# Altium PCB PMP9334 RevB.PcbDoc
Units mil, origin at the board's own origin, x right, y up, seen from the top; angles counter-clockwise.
Board outline 4000 x 1100 mil, 4 copper layers (Top Layer, MidLayer1, GND, Bottom Layer), stack 62 mil thick; 51 components, 29 nets, 117 pads, 95 vias.
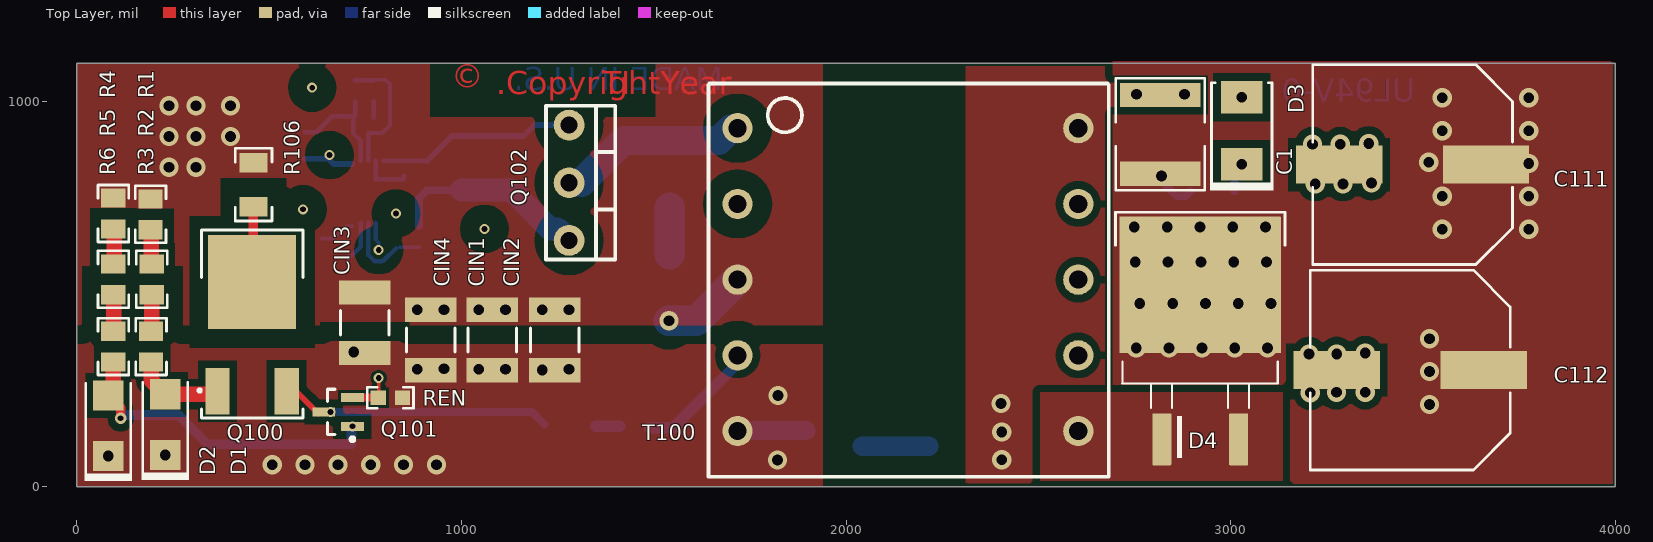
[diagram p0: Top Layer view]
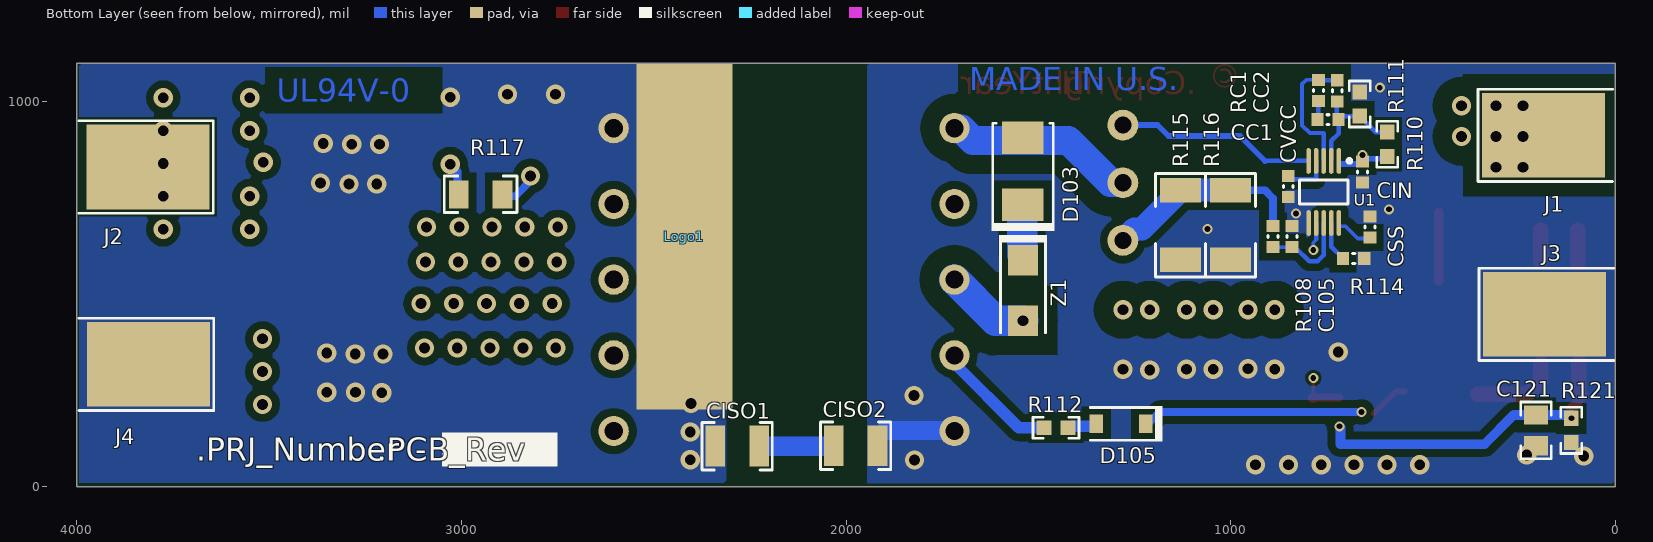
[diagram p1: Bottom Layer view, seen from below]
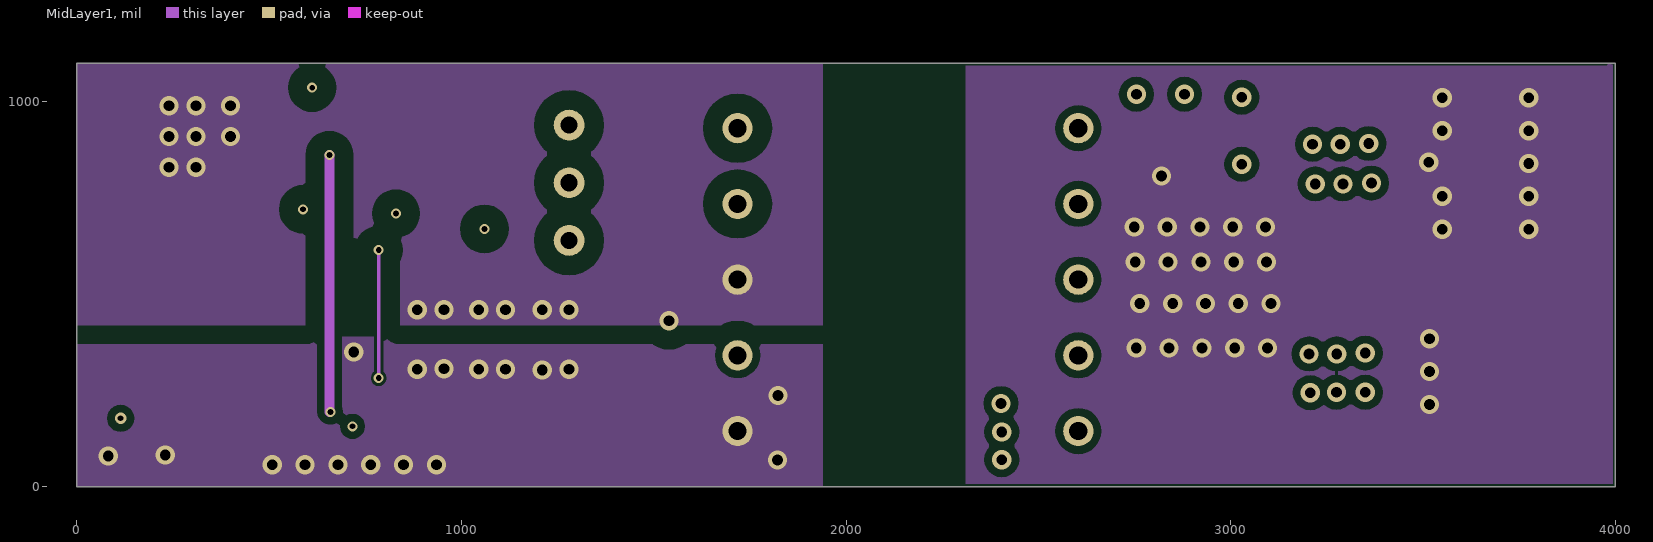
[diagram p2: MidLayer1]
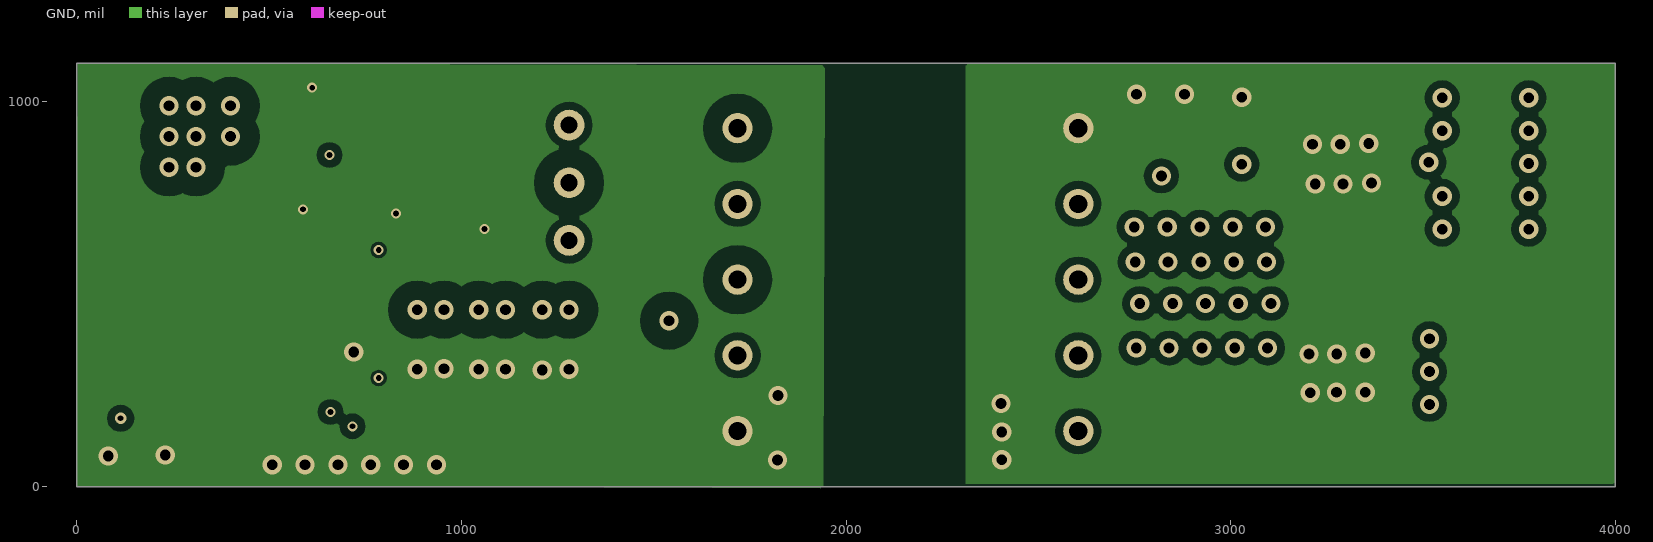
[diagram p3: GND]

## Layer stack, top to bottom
Top Solder: solder mask 0.4, Solder Resist, Dk 3.5
Top Layer: signal copper 1.4
Dielectric1: core 12.6, FR-4, Dk 4.8
MidLayer1: signal copper 0.7
Dielectric2: prepreg 32.6, FR-4, Dk 4.8
GND: signal copper 0.7
Dielectric3: core 12.6, FR-4, Dk 4.8
Bottom Layer: signal copper 1.4
Bottom Solder: solder mask 0.4, Solder Resist, Dk 3.5

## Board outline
0,0 4000,0 4000,1100 0,1100

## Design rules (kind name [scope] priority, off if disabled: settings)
AcuteAngle [All] p1: minimum=3.00000000000000E+0001 checktracksonly=FALSE
AssemblyTestPointUsage [All] p1: valid=2
Clearance Clearance_SYNC [InNet('SYNC') vs InNet('CS') or InNet('SS')] p1: gap=7.8
Clearance Clearance_UVLO [InNet('UVLO') vs InNet('CS') or InNet('GND')] p2: gap=7.8
Clearance Clearance_CS [InNet('CS') vs InNet('UVLO') or InNet('SYNC')] p3: gap=7.8
Clearance Clearance_FB [InNet('FB') vs InNet('VIN IC') or InNet('COMP')] p4: gap=7.8
Clearance Clearance_COMP [InNet('COMP') vs InNet('FB') or InNet('VCC')] p5: gap=7.8
Clearance Clearance_VCC [InNet('VCC') vs InNet('COMP') or InNet('OUT')] p6: gap=7.8
Clearance Clearance_MUB10A-N [HasFootprint('MUB10A_N') vs HasFootprint('MUB10A_N')] p7: gap=8
Clearance Clearance_R4 [InNet('NetR4_1') vs InNet('VIN HV')] p8: gap=30
Clearance Clearance_R1 [InNet('VIN HV') vs InNet('NetR1_1')] p9: gap=30
Clearance Clearance_ISO [InNet('ISO') vs InNet('GND') or InNet('ISO GND')] p10: gap=60
Clearance "Clearance_Snub PriSW" [InNet('SNUB SW') vs InNet('PRI SW')] p11: gap=50
Clearance Clearance_HV [InNetClass('50MIL')] p12: gap=50
Clearance Clearance_Poly [InPolygon] p13: gap=20
Clearance Clearance_BoardEdge_MountingHoles [OnCopper and InComponentClass('Mounting Holes') vs IsKeepOut] p14: gap=40
Clearance Clearance_BoardEdge_Poly [OnCopper and InPoly vs IsKeepOut] p15: gap=20
Clearance Clearance_BoardEdge [OnCopper and Not InComponentClass('Logo') and not InComponentClass('FiducialMark') and not InRegion(1000,500,4000,800) and Not IsKeepout vs IsKeepOut] p16: gap=75
Clearance [All] p17: gap=10
ComponentClearance ComponentClearance_Logo [InComponentClass(Logo)] p1 off: gap=50 collisioncheckmode=3 verticalgap=10 showdistances=FALSE
ComponentClearance ComponentClearance_ScrewToNut [(HasFootprint('NY PMS 440 0025 PH')) vs (HasFootprint('Keystone_1902C'))] p2 off: gap=5 collisioncheckmode=3 verticalgap=10 showdistances=FALSE
ComponentClearance ComponentClearance_MountingHoles [InComponentClass('Mounting Holes')] p3 off: gap=250 collisioncheckmode=3 verticalgap=100000 showdistances=FALSE
ComponentClearance ComponentClearance_SmallPassives [HasFootprint('0201*') or HasFootprint('0402*') or HasFootprint('0508') or HasFootprint('0603*') or HasFootprint('0612') or HasFootprint('0805*') or HasFootprint('0815*') or HasFootprint('0830*') or HasFootprint('1206*') or HasFootprint('1210*') or HasFootprint('1808*') or HasFootprint('1812*') or HasFootprint('1825*') or HasFootprint('2010*') or HasFootprint('2220*') or HasFootprint('2225*') or HasFootprint('2512*') or HasFootprint('2728*') or HasFootprint('3518*') vs HasFootprint('0201*') or HasFootprint('0402*') or HasFootprint('0508') or HasFootprint('0603*') or HasFootprint('0612') or HasFootprint('0805*') or HasFootprint('0815*') or HasFootprint('0830*') or HasFootprint('1206*') or HasFootprint('1210*') or HasFootprint('1808*') or HasFootprint('1812*') or HasFootprint('1825*') or HasFootprint('2010*') or HasFootprint('2220*') or HasFootprint('2225*') or HasFootprint('2512*') or HasFootprint('2728*') or HasFootprint('3518*')] p4 off: gap=20 collisioncheckmode=3 verticalgap=10 showdistances=FALSE
ComponentClearance ComponentClearance_THtoSMT [IsThruComponent vs IsSMTComponent] p5 off: gap=100 collisioncheckmode=3 verticalgap=100000 showdistances=FALSE
ComponentClearance ComponentClearance_THtoTH [IsThruComponent vs IsThruComponent] p6 off: gap=118.11 collisioncheckmode=3 verticalgap=100000 showdistances=FALSE
ComponentClearance [All] p7 off: gap=40 collisioncheckmode=3 verticalgap=10 showdistances=FALSE
DiffPairsRouting [All] p1: maxlimit=100 minlimit=10 mostfreqgap=10 toplayer_minwidth=15 toplayer_maxwidth=15 toplayer_prefwidth=15 midlayer1_minwidth=15 midlayer1_maxwidth=15 midlayer1_prefwidth=15 midlayer2_minwidth=15 midlayer2_maxwidth=15 midlayer2_prefwidth=15 bottomlayer_minwidth=15 bottomlayer_maxwidth=15 bottomlayer_prefwidth=15 maxuncoupledlength=1000
FabricationTestPointUsage TestPointUsage [All] p1: valid=2 allowmultiple=FALSE
FabricationTestpoint Testpoint [All] p1: side=3 testpointundercomponent=TRUE minsize=40 maxsize=100 preferedsize=60 minholesize=0 maxholesize=40 preferedholesize=32 testpointgrid=1 allowsidetop=TRUE allowsidebottom=TRUE usegrid=TRUE gridtolerance=0.01
FanoutControl Fanout_LCC [IsLCC] p1: bgadir=Out bgaviamode=Centered fanoutstyle=Auto fanoutdirection=Alternating viagrid=1 // Fanout_LCC (Default Rule)
FanoutControl Fanout_BGA [IsBGA] p2: bgadir=Out bgaviamode=Centered fanoutstyle=Auto fanoutdirection=Alternating viagrid=1 // Fanout_BGA (Default Rule)
FanoutControl Fanout_Default [All] p4: bgadir=Out bgaviamode=Centered fanoutstyle=Auto fanoutdirection=Alternating viagrid=1 // Fanout_Default (Default Rule)
FanoutControl Fanout_Small [(CompPinCount < 5)] p5: bgadir=Out bgaviamode=Centered fanoutstyle=Auto fanoutdirection=OutThenIn viagrid=1 // Fanout_Small (Default Rule)
HoleSize [All] p1: absolutevalues=TRUE maxlimit=251 minlimit=10 maxpercent=80.000 minpercent=20.000
MinimumAnnularRing [All] p1: minimumring=5
MinimumSolderMaskSliver MinimumSolderMaskSliver_Logo [InComponentClass('Logo') vs InComponentClass('Logo')] p1: minsoldermaskwidth=0
MinimumSolderMaskSliver [All] p2: minsoldermaskwidth=0
PlaneConnect [All] p1: planeconnectstyle=Direct reliefexpansion=10 reliefentries=4 reliefconductorwidth=10 reliefairgap=10
PolygonConnect [All] p1: connectstyle=Direct reliefconductorwidth=10 reliefentries=4 polygonreliefangle="90 Angle" airgapwidth=10
RoutingVias [All] p1: holewidth=15 width=24 viastyle="Through Hole" minholewidth=10 minwidth=26 maxholewidth=40 maxwidth=65
SMDToCorner [All] p1: distance=4000
SilkToSilkClearance [All] p1: silktosilkclearance=1
SilkToSolderMaskClearance SilkscreenOverComponentPads [IsPad] p1: minsilkscreentomaskgap=5 clearancetoexposedcopper=TRUE
SolderMaskExpansion [All] p1: expansion=3
UnpouredPolygon [All] p1: allowunpoured=FALSE
Width [All] p1: maxlimit=100 minlimit=6 preferedwidth=10 checkconnectedcopper=TRUE
15 further rules are at their usual default settings.

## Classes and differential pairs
component class Logo: Logo1
net class 50MIL: "NMOS DRAIN" "PRI SW" "VIN HV"

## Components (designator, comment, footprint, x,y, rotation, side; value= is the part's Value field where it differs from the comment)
C1 "TDK, C5750X7S2A106M" 2220 2817,916 r90 top
C105 "GRM2165C1H681JA01D" 0603L 840,650 r90 bottom
C111 "EMVY350ATR471MKE0S" CAPSMT_62_KE0 3473,837 r180 top
C112 "EMVY350ATR471MKE0S" CAPSMT_62_KE0 3467,303 r180 top
C121 "GRM21BR71E334KA01L" 0805_HV 206,146 r270 bottom
CC1 "C2012X7R1C474K" 0603L 747,953.95 r0 bottom
CC2 "GRM2165C1H331JA01D" 0603L 722.68,1029 r90 bottom
CIN "GRM32ER71H475KA88L" 0603L 657,818 r270 bottom
CIN1 "Kemet, C1812V473KDRACTU" 1812 1080.33,381 r270 top
CIN2 "Kemet, C1812V473KDRACTU" 1812 1243,381 r270 top
CIN3 "Kemet, C1812V473KDRACTU" 1812 749,426 r270 top
CIN4 "Kemet, C1812V473KDRACTU" 1812 920,381 r270 top
CISO1 "VJ1210A102JXGAT5Z" 1210 2283,105 r180 bottom
CISO2 "VJ1210A102JXGAT5Z" 1210 1975,106 r180 bottom
CSS "C2012X7R1C224K" 0603L 638,675 r90 bottom
CVCC "C2012X7R1E105K" 0603L 850,780 r270 bottom
D1 "CMZ5929B" SMA 230,161 r90 top
D2 "CMZ5913B" SMA 82,158 r90 top
D3 "SMBJ51A-13-F" SMB 3029,925 r90 top
D4 "MBRB20200CTT4G" DDPAK 2921,369 r90 top
D103 "1SMB5934BT3G" SMB 1540,820 r90 bottom
D105 "1N4148W-7-F" SOD-123 1285,163 r0 bottom
J1 "6091" 6091 2,913 r0 bottom
J2 "6091" 6091 4000,831 r180 bottom
J3 "6092" 6092 -1,448 r0 bottom
J4 "6092" 6092 3999,318 r180 bottom
Logo1 "Texas Instruments" TI_Stacked_SolderMask_Small 2420,650 r90 bottom
Q100 "Fairchild, FQD2N100" DPAK 456,390 r0 top
Q101 "CMST2222A" SOT-23 679.32,194 r180 top
Q102 "STP8NK100Z" TO220-3_A 1280,790 r0 top
R1 "CRCW0805200KJNEA" 0805_HV 192,708 r90 top
R2 "CRCW0805200KJNEA" 0805_HV 195,538.87 r90 top
R3 "CRCW0805200KJNEA" 0805_HV 193.32,364 r90 top
R4 "CRCW08051M00JNEA" 0805_HV 95,710 r90 top
R5 "CRCW08051M00JNEA" 0805_HV 95,538.87 r90 top
R6 "CRCW08051M00JNEA" 0805_HV 95,364 r90 top
R106 "CRCW12064K99FKEA" 1206 460,785 r90 top
R108 "CRCW0805499RFKEA" 0603L 890,650 r90 bottom
R110 "RG1608P-1872-B-T5" 0603 593,890 r270 bottom
R111 "CRCW06031K50FKEA" 0603 664.01,994.76 r270 bottom
R112 "CRCW060316R0JNEA" 0603 1454,153 r180 bottom
R114 "CRCW0805215KFKEA" 0603L 680,593 r0 bottom
R115 "CSRN2010FKR500" 2010 1130,680 r90 bottom
R116 "CSRN2010FKR500" 2010 1000,680 r90 bottom
R117 "CRCW1206100RFKEA" 1206 2950,760 r180 bottom
R121 "RC0603FR-07300KL" 0603 114,146 r90 bottom
RC1 "CRCW08051K87FKEA" 0603L 771.68,1030 r270 bottom
REN "RC0603FR-07300KL" 0603 815.32,231 r180 top
T100 "GCI Tech, G094215LF" "G094215LF r 0" 2161,538 r0 top locked
U1 "TI, LM5022MM" MUB10A_N 758,766 r270 bottom
Z1 "SMAJ120A" SMA 1540,510 r270 bottom

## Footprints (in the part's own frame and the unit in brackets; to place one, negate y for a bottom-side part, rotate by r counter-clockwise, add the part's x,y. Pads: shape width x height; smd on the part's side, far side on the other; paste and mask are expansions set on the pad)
0603 [mm] "0603 from SM-752 data"
  rect 1x0.95 smd: 1(-0.8,0) 2(0.8,0)
  silkscreen extent -1.52,-0.69 1.52,0.69, body extent -0.87,-0.47 0.87,0.47, height 0.85
0603L [mm] "0603 from SM-752 data"
  rect 0.8x0.85 smd: 1(-0.7,0) 2(0.7,0)
  silkscreen extent -0.07,-0.33 0.07,0.33, body extent -0.87,-0.47 0.87,0.47, height 0.85
0805_HV [mil] "0805 with 30mil clearance between pads"
  rect 50x63 smd: 1(-40,0) 2(40,0)
  silkscreen extent -74,-40 74,40, body extent -43,-29 43,29, height 43
1206 [mm] "1206 from SM-752 data"
  rect 1.3x1.85 smd: 1(-1.45,0) 2(1.45,0)
  silkscreen extent -2.4,-1.21 2.4,1.21, body extent -1.7,-0.9 1.7,0.9, height 1.35
1210 [mm] "1210 from SM-752 data"
  rect 1.3x2.7 smd: 1(-1.45,0) 2(1.45,0)
  silkscreen extent -2.32,-1.57 2.32,1.57, body extent -1.7,-1.35 1.7,1.35, height 1.35
1812 [mm]
  rect 1.6x3.4 smd: 1(-2,0) 2(2,0)
  silkscreen extent -0.8,-1.6 0.8,1.6, body extent -2.4,-1.7 2.4,1.7, height 1.35
2010 [mm] "Chip Capacitor, Body 5.08x2.54mm, IPC Medium Density"
  rect 1.6x2.7 smd: 1(-2.3,0) 2(2.3,0)
  silkscreen extent -3.42,-1.65 3.42,1.65, body extent -2.73,-1.45 2.73,1.45, height 1.66
2220 [mm] "Chip Capacitor, Body 5.7x5.0mm, IPC Medium Density"
  rect 1.6x5.3 smd: 1(-2.6,0) 2(2.6,0)
  silkscreen extent -3.69,-2.94 3.69,2.94, body extent -2.95,-2.62 2.95,2.62, height 1.35
6091 [mil] "Keystone Insulated End Launch Banana Jack"
  rect 320x220 smd: 1(185,0)
  silkscreen extent 5,-120 355,120, body extent -666,-216 271,216, height 227
6092 [mil] "Keystone Insulated End Launch Banana Jack"
  rect 320x220 smd: 1(185,0)
  silkscreen extent 5,-120 355,120, body extent -666,-216 271,216, height 227
CAPSMT_62_KE0 [mm] "12.5 x 13.5mm:  Chemi-Con KE0"
  rect 5.7x2.5 smd: 1(-4.85,0) 2(4.85,0)
  silkscreen extent -6.6,-6.6 6.6,6.6, body extent -6.6,-6.6 6.6,6.6, height 14
DDPAK [mil] "D2-PAK, 3-Pads, Body 9.7x10.4mm (max), TO-263AB, using Vishay Silionix recommended pad sizes"
  rrect8% 135x49.49 smd: 1(-246.06,100) 3(-246.06,-100)
  rrect1% 355x420 smd paste-181.1: 4(155.51,0)
  silkscreen extent -295,-220 344,220, body extent -295,-202 324,202, height 180
DPAK [mm]
  rect 5.8x6.2 smd: D(0,3.61)
  rect 1.6x3.05 smd: G(-2.28,-3.61) S(2.28,-3.61)
  silkscreen extent -3.55,-5.39 3.35,7.04, body extent -3.35,-0.74 3.35,5.46, height 2.39
"G094215LF r 0" [mm]
  round 2 hole 1.2: 1(-11.25,10) 2(-11.25,5) 3(-11.25,0) 4(-11.25,-5) 5(-11.25,-10) 6(11.25,-10) 7(11.25,-5) 8(11.25,0) 9(11.25,5) 10(11.25,10)
  silkscreen extent -13.18,-13.01 13.26,12.95
MUB10A_N [mm] "TSSOP, 10-Leads, Body 3x3mm, Pitch 0.5mm, IPC Medium Density"
  oval 1.7x0.3 smd: 1(-2.05,1) 2(-2.05,0.5) 3(-2.05,0) 4(-2.05,-0.5) 5(-2.05,-1) 6(2.05,-1) 7(2.05,-0.5) 8(2.05,0) 9(2.05,0.5) 10(2.05,1)
  silkscreen extent -2.17,-1.6 0.8,1.82, body extent -1.6,-1.6 1.6,1.6, height 1.09
SMA [mm] "Molded Diode, 2-Leads, Body 4.3x2.6mm, IPC Medium Density, based on OnSemi component dimensions and land pattern"
  rect 2x2 smd: 1(-2,0) 2(2,0)
  silkscreen extent -3.66,-1.57 2.79,1.57, body extent -2.6,-1.3 2.6,1.3, height 2.42
SMB [mil] "Molded Diode, 2-Leads, Body 5.4x3.6mm, IPC Medium Density, based on OnSemi component dimensions"
  rect 85x107.99 smd: 1(-87.01,0) 2(87.01,0)
  silkscreen extent -155,-82 125,82, body extent -106,-71 106,71, height 91
SOD-123 [mm] "On Semi recommended land pattern"
  rect 0.915x1.22 smd: 1(-1.637,0) 2(1.637,0)
  silkscreen extent -2.74,-1.17 2.03,1.17, body extent -1.93,-0.9 1.93,0.9, height 1.35
SOT-23 [mm] "SOT23, 3-Leads, Body 2.9x1.3mm, Pitch 0.95mm, Lead Span 2.5mm, IPC Medium Density"
  rect 1.5x0.6 smd: 1(-0.95,0.95) 2(-0.95,-0.95) 3(0.95,0)
  silkscreen extent -1.07,-1.5 0.7,1.92, body extent -1.16,-1.45 1.21,1.45, height 1
TI_Stacked_SolderMask_Small [mil]
  rect 900x250 smd paste-125 mask-125: 0(0,0)
TO220-3_A [mil]
  round 80 hole 45: 1(0,150) 2(0,0) 3(0,-150)
  silkscreen extent -60,-200 120,200

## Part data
C1: library part C5750X7S2A106M, "CAP, CERM, 10uF, 100V, +/-20%, X7S, 2220"
C105: "CAP, CERM, 680pF, 50V, +/-5%, C0G/NP0, 0805"
C111 C112: "CAP, AL, 470uF, 35V, +/-20%, 0.07 ohm, SMD"
C121: "CAP, CERM, 0.33uF, 25V, +/-10%, X7R, 0805"
CC1: "CAP, CERM, 0.47uF, 16V, +/-10%, X7R, 0805"
CC2: "CAP, CERM, 330pF, 50V, +/-5%, C0G/NP0, 0805"
CIN: "CAP, CERM, 4.7uF, 50V, +/-10%, X7R, 1210"
CIN1 CIN2 CIN3 CIN4: library part WB_CAPACITOR, "Capacitor"
CISO1 CISO2: "CAP, CERM, 1000 pF, 1000 V, +/- 5%, C0G/NP0, 1210"
CSS: "CAP, CERM, 0.22uF, 16V, +/-10%, X7R, 0805"
CVCC: "CAP, CERM, 1uF, 25V, +/-10%, X7R, 0805"
D1 D2: library part WB_Zener
D3: "Diode, TVS, Uni, 51V, 600W, SMB"
D4: "Diode, Schottky, 200V, 20A, DDPAK"
D103: "Diode, Zener, 24V, 550mW, SMB"
D105: "Diode, Ultrafast, 100V, 0.15A, SOD-123"
J1 J2: "Standard Banana Jack, Insulated, Red"
J3 J4: "Standard Banana Jack, Insulated, Black"
Logo1: library part TI_Logo, "Texas Instrument Corporate Signature"
Q100: library part WB_N_MOSFET, "N-Channel MOSFET"
Q101: library part WB_NPN_CMST2222A, "NPN Bipolar Transistor"
Q102: library part FET-N_T0-220, "MOSFET"
R1 R2 R3: "RES, 200k ohm, 5%, 0.125W, 0805"
R4 R5 R6: "RES, 1.0Meg ohm, 5%, 0.125W, 0805"
R106: "RES, 4.99k ohm, 1%, 0.25W, 1206"
R108: "RES, 499 ohm, 1%, 0.125W, 0805"
R110: "RES, 18.7k ohm, 0.1%, 0.1W, 0603"
R111: "RES, 1.50 k, 1%, 0.1 W, 0603"
R112: "RES, 16 ohm, 5%, 0.1W, 0603"
R114: "RES, 215k ohm, 1%, 0.125W, 0805"
R115 R116: "RES, 0.5, 1%, 1 W, 2010"
R117: "RES, 100 ohm, 1%, 0.25W, 1206"
R121 REN: "RES, 300k ohm, 1%, 0.1W, 0603"
RC1: "RES, 1.87k ohm, 1%, 0.125W, 0805"
T100: library part XFMR-EFD15-2P-1S
U1: library part LM5022MM, "60V Low Side  Controller for Boost and SEPIC"
Z1: "Diode, TVS, Uni, 120V, 400W, SMA"

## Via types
v1: diameter 50, hole 28, Top Layer to Bottom Layer, tented both sides, 85 vias
v2: diameter 26, hole 15, Top Layer to Bottom Layer, tented both sides, 9 vias
v3: diameter 30, hole 15, Top Layer to Bottom Layer, tented both sides, 1 vias

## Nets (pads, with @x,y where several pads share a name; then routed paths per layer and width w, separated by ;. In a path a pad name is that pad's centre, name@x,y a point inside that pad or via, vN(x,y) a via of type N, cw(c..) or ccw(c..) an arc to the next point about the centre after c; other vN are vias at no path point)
ANODE: D105.2 R112.2 | length 62.6
  Bottom Layer w30: D105.2@1349.43,157 R112.2@1412,157
"AUX SW": R112.1 T100.4 | length 298.9
  Bottom Layer w30: R112.1@1488.43,153 1551,153 T100.4@1718.09,320.09
COMP: CC2.2 RC1.1 U1.3 | length 337.1
  Bottom Layer w10: 759,919 794,919 814.01,939.01 814.01,1046.76 803.21,1057.56 RC1.1
  Bottom Layer w11.8: CC2.2 RC1.1@770.68,1056.56 ; U1.3 758,918
CS: C105.1 R108.1 U1.8 | length 226
  Bottom Layer w10: C105.1 R108.1
  Bottom Layer w11.8: U1.8 758,602 774,586 796,586 C105.1@830,620
FB: CC1.1 CC2.1 R110.1 R111.2 U1.2 | length 300.2
  Bottom Layer w11.8: R110.1 622.25,921.5 R111.2 724.01,963.26 CC2.1@724.01,1000.11 ; CC1.1 719.44,917.56 738.31,898.69 U1.2
GND: C105.2 C121.2 CIN1.2 CIN2.2 CIN3.2 CIN4.2 CIN.2 CISO2.2 CSS.2 CVCC.2 D1.1 D2.1 J3.1 R111.1 R114.1 R115.1 R116.1 R121.1 REN.1 T100.5 U1.6 | length 176.5
  Bottom Layer w50: T100.5@1719.79,146 CISO2.2@1896.32,146
  other v1: 508.33,57 593.67,57 679,57 764.33,57 849.67,57 935,57 1822,69 82,79.26 230,82.26 1823,237 1210,303.2 885,305 1045,305 1115,305 1280,305 955,306.2 720,350
  other v2: 1060,670 830,710 588,721 612,1037
ISO: CISO1.2 CISO2.1 | length 174.1
  Bottom Layer w50: CISO2.1@2041.93,105 CISO1.2@2216.07,105
"ISO GND": C1.2 C111.2 C112.2 CISO1.1 D3.2 J4.1 Logo1.0 T100.10
  other v1: 2405,70 2405,142 2403,216 3207.16,243.94 3275,245 3350,245 3204,345 3276,345 3350,347 3220,787 3292,787 3366,789 3213,890 3285,890 3359,892 3029,1012.01 2755,1020 2880,1020
NetCC1_2: CC1.2 RC1.2 | length 43.9
  Bottom Layer w11.8: CC1.2@771.68,958.55 RC1.2
NetD3_1: D3.1 R117.1 | length 77.8
  Bottom Layer w20: R117.1@3010.09,768 3010.09,819.08 v1(3029,837.99)
NetD4_1: D4.1 D4.3 T100.6
NetR1_1: R1.1 R2.2 | length 80
  Top Layer w40: R2.2@193.32,586 R1.1@193.32,665.99
NetR2_1: R2.1 R3.2 | length 88.3
  Top Layer w40: R3.2@195,407.29 R2.1@195,495.58
NetR4_1: R4.1 R5.2 | length 84.5
  Top Layer w40: R5.2@97,582.18 R4.1@97,666.69
NetR5_1: R5.1 R6.2 | length 82.7
  Top Layer w40: R6.2@96.01,407.31 R5.1@96.01,490
"NMOS DRAIN": Q100.D R106.1 | length 177.9
  Top Layer w25: Q100.D@459,535.13 R106.1@459,713
"NMOS GATE": D1.2 Q100.G R3.1 | length 224.3
  Top Layer w40: R3.1@193.32,320.71 193.32,276.43 D1.2 Q100.G@358.1,239.74
"NPN BASE": C121.1 D2.2 Q101.1 R6.1 R121.2 | length 822.8
  Top Layer w25: D2.2 114,204.74 v3(114,177.5)
  Top Layer w40: D2.2@95,249.74 R6.1
  Bottom Layer w25: R121.2@114,186 C121.1 264,186 340,110 714.32,110 v2@714.32,154.2
  other v2: 716.72,156.6
OUT: Q102.1 U1.5 | length 521.3
  Bottom Layer w11.8: U1.5 910.71,846.71
  Bottom Layer w15: 910.71,846.71 975.62,911.62 1161.62,911.62 1190,940 Q102.1
"PRI SW": D103.2 Q102.2 T100.1 | length 478
  Bottom Layer w75: Q102.2 1312,790 1422,900 1670,900 T100.1@1700,930
"SNUB SW": D103.1 Z1.1 | length 120
  Bottom Layer w80: Z1.1@1542,605 D103.1@1542,724.99
SOURCE: Q102.3 R108.2 R115.2 R116.2 | length 524.9
  Bottom Layer w20: R108.2 890,750 910.55,770.55 R116.2
  Bottom Layer w60: R116.2 R115.2 ; R115.2@1130,770.29 1230.29,670 1250,670 Q102.3
SS: CSS.1 U1.10 | length 91.1
  Bottom Layer w10: CSS.1@638,645.44 669.44,645.44 701,677 U1.10@716,677
SYNC: R114.2 U1.9 | length 104.6
  Bottom Layer w11.8: R114.2 738,623.44 ; 738.31,623.76 U1.9
UVLO: Q101.2 REN.2 U1.7 | length 522.4
  Top Layer w10: REN.2@785,232.18 v2(785,282)
  Top Layer w20: Q101.2 REN.2@780.89,231.4
  Top Layer w25: REN.2@783.82,231.4 REN.2@787.35,231.4
  MidLayer1 w10: v2(785,282) v2@785,614
  Bottom Layer w8: 777,641.98 785,633.98
  Bottom Layer w10: v2(785,615) 785,633.98
  Bottom Layer w11.8: 777.68,642.67 U1.7
VCC: CVCC.1 U1.4 | length 127.5
  Bottom Layer w11.8: U1.4 777.76,846.71 777.76,799.54 850,799.54 CVCC.1
"VIN HV": CIN1.1 CIN2.1 CIN3.1 CIN4.1 J1.1 R1.2 R4.2 R106.2 T100.3 Z1.2 | length 222.3
  Bottom Layer w80: v1(1540,431.26) 1611.35,431.26 T100.3
  other v1: 885,460 955,460 1045,460 1115,460 1210,460 1280,460 240,830 310,830 240,910 310,910 400,910 240,990 310,990 400,990
"VIN IC": CIN.1 D105.1 Q100.S Q101.3 R110.2 U1.1 | length 1489.4
  Top Layer w15: Q100.S@546.64,247 570.79,247 Q101.3@627.73,190.05 ; v2(659.63,194) Q101.3@659.63,197.69
  MidLayer1 w8: v2@651.32,203.4 651.32,206 659.63,197.69 v2(659.63,194)
  MidLayer1 w25: v2@657,194 v2(657,862)
  Bottom Layer w15: R110.2@593,852.5 653.06,852.5 CIN.1@650.56,855 ; CIN.1@658.5,847.06 666.85,838.71 U1.1@716.23,838.71
  Bottom Layer w20: v2(659.63,194) 1183.53,194 D105.1@1216.27,161.27
VOUT: C1.1 C111.1 C112.1 D4.4 J2.1 R117.2 | length 104.9
  Bottom Layer w20: v1@2815,799.86 2859.86,755 2882.91,755 R117.2@2895.91,768
  other v1: 3517,213.67 3517,299 2754.67,360 2840,360 2925.33,360 3010.67,360 3096,360 3517,384.33 2763.96,475.89 2849.3,475.89 2934.63,475.89 3019.96,475.89 3105.3,475.89 2752.15,583.69 2837.49,583.69 2922.82,583.69 3008.15,583.69 3093.49,583.69 3550,669.33 3775,669.33 2749.67,675 2835,675 2920.33,675 3005.67,675 3091,675 3550,754.67 3775,754.67 2820,807.73 3775,840 3515,843 3550,925.33 3775,925.33 3550,1010.67 3775,1010.67
pads on no net: T100.2 T100.7 T100.8 T100.9

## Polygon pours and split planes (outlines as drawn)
"ISO GND" on GND "ISO GND" (solid, pour order 45): 2312.33,1093.92 2317.86,1100 4000,1100 4000,0 3993.63,7 2311.16,7 2311.16,1100
GND on GND "GND" (solid, pour order 44): 0,550 2.79,1101 1944.21,1095 1945,1089 1940.2,-5.01 1370.25,-2 1368.39,0 0,0
GND on MidLayer1 "Mid Layer-GND" (solid, remove dead copper, pour order 43): 0,0 0,390 1940,390 1940,0 0,0
"VIN HV" on MidLayer1 "Mid Layer-VIN" (solid, remove dead copper, pour order 42): 0,1100 1940,1100 1940,420 0,420 0,1100
VOUT on MidLayer1 "MidLayer1-VOUT" (solid, pour order 41): 2312.33,1093.92 3977.46,1093.92 3988.45,1106 3993,1101 3993,7 2311.16,7 2311.16,1093.79
"ISO GND" on Bottom Layer "L4 RTN" (solid, pour order 47): 2309,1100 3982.95,1100 3984.56,1101.76 3993,1092.52 3993,10 2318.14,10 2312.87,4.24 2311.16,6.11 2311.16,1100
GND on Bottom Layer "L4 gnd" (solid, remove dead copper, pour order 46): 0,1100 1362.43,1100 1945,1101.63 1945,8.63 6.48,7 2.78,3 2.78,1101
"VIN HV" on Top Layer "Top Layer-VIN" (solid, remove dead copper, pour order 38): 0,1100 1940,1100 1940,420 0,420 0,1100
GND on Top Layer "Top Layer-GND" (solid, remove dead copper, pour order 40): 0,0 0,390 1940,390 1940,0 0,0
VOUT on Top Layer "L1 out" (solid, pour order 37): 2693,1106 3988,1106 3996,1098 3993,1095 3993,7 2696,7 2693,10
"ISO GND" on Top Layer "L1 RTN" (solid, pour order 39): 2312.08,1092.93 2693.54,1092.93 2702.16,1105.01 2702.16,9.01 2321.86,9.01 2314.73,-0.99 2311.16,4.01 2311.16,1092.79
NetD4_1 on Top Layer "Top Layer-D4" (solid, remove dead copper, pour order 36): 2505,245 3135,245 3135,15 2505,15 2505,245

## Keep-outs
Keep-Out Layer:
  text ".Layer_Name" at 577,-2258.49 h60

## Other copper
Top Layer:
  text ".CopyrightYear" at 1090,1020 h60
  text "TI" at 1366,1020 h60
  text "©" at 973,1016.48 h105
  text ".Layer_Name" at 577,-2258.49 h60
Bottom Layer:
  text "MADE IN U.S." at 1680,1030 h60
  text "UL94V-0" at 3480,1000 h60
  text ".VersionControl_RevNumber" at 4031,-320.5 h60
  text "SVN:" at 4310,-320.5 h60
  text ".Layer_Name" at 577,-2258.49 h60

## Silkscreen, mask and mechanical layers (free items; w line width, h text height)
Top Overlay:
  text ".Layer_Name" at 577,-2258.49 h40
Bottom Overlay:
  rectangle: 2750,52 3050,140
  text "-" at 3120,67 h60
  text ".PCB_Rev" at 3220,67 h60
  text ".PRJ_Number" at 3690,67 h60
  text ".Layer_Name" at 577,-2258.49 h60
Top Paste:
  text ".Layer_Name" at 577,-2258.49 h60
Bottom Paste:
  text ".Layer_Name" at 577,-2258.49 h60
Top Solder:
  text ".Layer_Name" at 577,-2258.49 h60
  text ".Layer_Name" at 577,-2258.49 h60
Bottom Solder:
  text ".Layer_Name" at 577,-2258.49 h60
Drill Guide:
  text ".Layer_Name" at 577,-2258.49 h60
M1 Board Outline:
  the board outline again, w10
  text ".Layer_Name" at 577,-2258.49 h60
M2 Board Dimensions:
  rectangle: -0.5,-1685.5 124.5,-1560.5
  rectangle: 124.5,-1810.5 499.5,-1685.5
  lines w7: -0.5,-1685.5 999.5,-1685.5 ; 124.5,-1810.5 124.5,-1560.5 ; 249.5,-1810.5 249.5,-1560.5 ; 499.5,-1810.5 499.5,-1560.5 ; 749.5,-1810.5 749.5,-1560.5 ; -0.5,-1810.5 999.5,-1810.5 999.5,-1560.5 -0.5,-1560.5 -0.5,-1810.5
  lines w10: -134.99,82.92 -114.99,22.92 ; -134.99,1062.92 -114.99,1122.92 ; -124.99,22.92 -104.99,22.92 ; -124.99,1122.92 -104.99,1122.92 ; -114.99,302 -114.99,22.92 ; -114.99,843.84 -114.99,1122.92 ; -94.99,82.92 -114.99,22.92 ; -94.99,1062.92 -114.99,1122.92 ; -0.5,-1875.5 -0.5,-1855.5 ; 59.5,-1885.5 -0.5,-1865.5 ; 59.5,-1845.5 -0.5,-1865.5 ; 223.58,-1865.5 -0.5,-1865.5 ; 775.42,-1865.5 999.5,-1865.5 ; 939.5,-1885.5 999.5,-1865.5 ; 939.5,-1845.5 999.5,-1865.5 ; 999.5,-1875.5 999.5,-1855.5
  text "1100 (mil)" at -79,312 h60 r90
  text "1000 (mil)" at 233.58,-1901.49 h60
  text ".Layer_Name" at 577,-2258.49 h60
M3 3D STEP Top:
  text ".Layer_Name" at 577,-2258.49 h60
M4 3D STEP Bottom:
  text ".Layer_Name" at 577,-2258.49 h60
M5 Assembly Top:
  lines w7: 5139,-1289.5 6264,-1289.5 ; 5139,-1167 6261.5,-1167 ; 5454,-1409.5 5454,-1047 ; 5839,-1409.5 5139,-1409.5 ; 5839,-1047 5139,-1047 ; 5139,-1409.5 6264,-1409.5 6264,-1047 5139,-1047 ; 5139,-1409.5 5139,-1047
  lines w10: -292,-2330.17 6308,-2330.17 ; -292,-2126.83 6310,-2126.83 ; -292,-1923.5 -292,-2533.5 3713,-2533.5 6310,-2533.5 6310,-1923.5 -291.5,-1923.5 -291.5,-2533.5 1284,-2533.5 ; 2173,-2533.5 2173,-1923.5 ; 3440,-2126.83 3440,-1923.5 ; 4280,-2126.83 4280,-1923.5 ; 4902,-2540 4902,-2337.17
  text "TABLE 1" at 5526.5,-1012 h40
  text "Variant" at 5164,-1122 h40
  text "Label text" at 5599,-1122 h40
  text "001" at 5231.5,-1242 h40
  text "ChangeMe!" at 5509,-1244.5 h40
  text "002" at 5231.5,-1367 h40
  text "ChangeMe!" at 5504,-1369.5 h40
  text "COMPONENTS MARKED 'DNP' SHOULD NOT BE POPULATED." at 1153.5,-1718.5 h60
  text "ASSEMBLY VARIANT:" at 1153,-1834 h60
  text ".VariantName" at 2189,-1834 h60
  text "PCB VIEWED FROM TOP SIDE" at -228.5,-2055.67 h60
  text "BOARD #:" at 2248,-2055.67 h60
  text ".PRJ_Number" at 2793.5,-2055.67 h60
  text "REV:" at 3638,-2055.67 h60
  text ".PCB_Rev" at 3929.5,-2055.67 h60
  text "SVN REV:" at 4476,-2055.67 h60
  text ".VersionControl_RevNumber" at 4982,-2055.67 h60
  text "IGNORE ->" at -228.5,-2258.49 h60
  text "PLOT NAME =" at -228.5,-2464.34 h60
  text ".plot_File_Name" at 577,-2464.34 h60
  text "GENERATED    :" at 2250,-2464.34 h60
  text ".Print_Date" at 3119.5,-2464.34 h60
  text ".Print_Time" at 3848.5,-2464.34 h60
  text "TEXAS INSTRUMENTS" at 5113,-2464.34 h60
M6 Assembly Bottom:
  lines w10: -292.5,-2127.33 6309.5,-2127.33 ; -290.5,-2330.67 6309.5,-2330.67 ; 1115.5,-2540.5 1115.5,-2337.67 ; 1737.5,-2127.33 1737.5,-1924 ; 2577.5,-2127.33 2577.5,-1924 ; 3844.5,-2534 3844.5,-1924 ; 4733.5,-2534 6309,-2534 6309,-1924 -292.5,-1924 -292.5,-2534 2304.5,-2534 6309.5,-2534 6309.5,-1924
  text "COMPONENTS MARKED 'DNP' SHOULD NOT BE POPULATED." at 6102,-1718 h60
  text ".VariantName" at 5058,-1834 h60
  text "ASSEMBLY VARIANT:" at 6097,-1834 h60
  text ".VersionControl_RevNumber" at 1035.5,-2056.17 h60
  text "SVN REV:" at 1541.5,-2056.17 h60
  text ".PCB_Rev" at 2088,-2056.17 h60
  text "REV:" at 2379.5,-2056.17 h60
  text ".PRJ_Number" at 3224,-2056.17 h60
  text "BOARD #:" at 3769.5,-2056.17 h60
  text "PCB VIEWED FROM BOTTOM SIDE" at 6246,-2056.17 h60
  text "IGNORE ->" at 2547.85,-2258.49 h60
  text "TEXAS INSTRUMENTS" at 904.5,-2464.84 h60
  text ".Print_Time" at 2169,-2464.84 h60
  text ".Print_Date" at 2898,-2464.84 h60
  text "GENERATED    :" at 3767.5,-2464.84 h60
  text ".plot_File_Name" at 5440.5,-2464.84 h60
  text "PLOT NAME =" at 6246,-2464.84 h60
M9 Title Sheet:
  drawing of 57 lines, arcs and shapes, not listed
  text "1" at 739.84,6636.5 h70
  text "2" at 3235.5,6636.5 h70
  text "3" at 5724.84,6636.5 h70
  text "4" at 8231.51,6636.5 h70
  text "5" at 10730.5,6636.5 h70
  text "6" at 13235.5,6636.5 h70
  text "A" at -416.5,5493.5 h70
  text "A" at 14383.5,5493.5 h70
  text "B" at -416.5,3113.5 h70
  text "B" at 14383.5,3113.5 h70
  text "C" at -416.5,738.5 h70
  text "C" at 14383.5,738.5 h70
  text "PROJECT TITLE:" at 11343.5,-1122.5 h45
  text ".PRJ_Title" at 11393.5,-1255.83 h70
  text "DESIGNED FOR:" at 11343.5,-1423.5 h45
  text ".PRJ_Customer" at 11393.5,-1563.5 h70
  text "D" at -416.5,-1631.5 h70
  text "D" at 14383.5,-1631.5 h70
  text "FILE NAME:" at 11343.5,-1723.5 h45
  text ".PCB_File_Name_No_Path" at 11393.5,-1843.5 h70
  text "Texas Instruments (TI) and/or its licensors do not warrant the accuracy or completeness of this specification" at 6374,-2005.34 h45
  text "ENGINEER:" at 11343.5,-2013.5 h45
  text "LAYOUT BY:" at 12848.5,-2013.5 h45
  text "or any information contained therein. TI and/or its licensors do not warrant that this design will meet" at 6329.01,-2118 h45
  text ".PRJ_Engineer" at 11393.5,-2168.49 h70
  text ".PCB_Layout" at 12899,-2168.49 h70
  text "the specifications, will be suitable for your application or fit for any particular purpose, or will operate in" at 6329.01,-2230.67 h45
  text ".Layer_Name" at 577,-2258.49 h60
  text "ALTIUM DESIGNER VERSION:" at 12848.5,-2323.5 h45
  text "an implementation. TI and/or its licensors do not warrant that the design is production worthy. You should" at 6329.01,-2343.33 h45
  text "completely validate and test your design implementation to confirm the system functionality for your application." at 6374,-2456 h45
  text ".print_Scale" at 11393.5,-2456.83 h70
  text ".Application_BuildNumber" at 12899,-2456.83 h70
  text "1" at 739.84,-2663.5 h70
  text "2" at 3235.5,-2663.5 h70
  text "3" at 5724.84,-2663.5 h70
  text "4" at 8231.51,-2663.5 h70
  text "5" at 10730.5,-2663.5 h70
  text "6" at 13235.5,-2663.5 h70
M10 Fab Notes:
  drawing of 207 lines, arcs and shapes, not listed
  text "DESIGN INFORMATION" at 12381.02,5410 h60
  text "(REFER ALSO ARRAY/PANEL PROFILING INFORMATION)" at 12019.46,5248.29 h60
  text "BOARD SIZE" at 11333.46,5244 h60
  text "3999MIL" at 11795.78,5116.18 h60
  text "X" at 12301.46,5116.18 h60
  text "1100MIL" at 12532.78,5116.18 h60
  text "Number of Layers :" at 11736.46,4919 h60
  text "4" at 12831.27,4909 h60
  text "MIN. TRACK WIDTH:" at 11736.46,4780 h60
  text "10" at 12832.7,4780 h60
  text "MIL" at 12987.46,4780 h60
  text "MIN. CLEARANCE:" at 11736.46,4648 h60
  text "7.8" at 12832.7,4648 h60
  text "MIL" at 12987.46,4648 h60
  text "MIN. VIA PAD SIZE:" at 11736.46,4516 h60
  text "10" at 12802.71,4516 h60
  text "MIL" at 12987.46,4516 h60
  text "0.125mm (5MIL)" at 12431.46,4374.29 h60
  text "MINIMUM ANNULAR RING" at 11407.23,4370 h60
  text "EXTERNAL" at 13139.46,4370 h60
  text "PER" at 11607.23,4252 h60
  text "IPC-D-275 CLASS 2 LEVEL C" at 11827.23,4252 h60
  text "MIL, HOLES" at 13315.46,4139.71 h60
  text "+/-" at 12923,4139 h60
  text "+/-" at 13777,4139 h60
  text "REGISTRATION TOLERANCES:" at 11407.23,4134 h60
  text "METAL" at 12607,4134 h60
  text "5" at 13183.2,4134 h60
  text "3" at 14016.2,4134 h60
  text "MIL" at 14132.46,4134 h60
  text "MATERIAL:" at 11332.46,3924.54 h60
  text "FR-4 High Tg" at 12318.9,3784.21 h60
  text "FR-4" at 11793.46,3775.64 h60
  text "OTHER" at 13241.46,3775.64 h60
  text "X" at 11600,3770 h60
  text "62 MIL (1.6mm) +/-10%" at 12073.56,3612.92 h60
  text "THICKNESS:" at 11407.23,3608.64 h60
  text "X" at 11945.4,3608.64 h60
  text "OTHER" at 13358.46,3608.64 h60
  text "TOLERANCE:" at 11407.23,3450.64 h60
  text "X" at 12246.53,3450.64 h60
  text "ANSI IPC-6012 TYPE 3 CLASS 2" at 12433.48,3450.64 h60
  text "OTHER +/-" at 12433.46,3294.64 h60
  text "BOW & TWIST:" at 11407.23,3137.64 h60
  text "X" at 12246.53,3137.64 h60
  text "ANSI IPC-6012 TYPE 3 CLASS 2" at 12433.48,3137.64 h60
  text "OTHER +/-" at 12433.46,2979.13 h60
  text "COPPER THICKNESS (FINISHED):" at 11332.46,2843.64 h60
  text "1.4MIL (1oz)" at 12212.46,2690.92 h60
  text "2MIL (1.4oz)" at 12979.46,2690.92 h60
  text "2.8MIL (2oz)" at 13706.46,2690.92 h60
  text "OUTER:" at 11689.46,2686.64 h60
  text "X" at 12084,2686 h60
  text "0.7MIL (0.5oz)" at 12212.46,2533.92 h60
  text "2.8MIL (2oz)" at 12979.46,2533.92 h60
  text "N/A" at 13706,2534.29 h60
  text "INNER SIGNAL:" at 11400.38,2529.64 h60
  text "X" at 12085.42,2529.64 h60
  text "DRILLING:" at 11332.46,2390.64 h60
  text "REFERENCE:" at 11407.23,2273.64 h60
  text "X" at 12055.46,2273.64 h60
  text "AS SHOWN" at 12242.46,2273.64 h60
  text "X" at 12956.46,2273.64 h60
  text "NC_DRILL FILES" at 13093.46,2273.64 h60
  text "PTH MIN COPPER THICKNESS:" at 11407.23,2115.64 h60
  text "X" at 12757.46,2115.64 h60
  text "1MIL" at 12894.46,2115.64 h60
  text "OTHER" at 13391.46,2115.64 h60
  text "BOARD FINISH:" at 11332.46,1956.64 h60
  text "SILKSCREEN:" at 11487.68,1838.64 h60
  text "X" at 12436.46,1838.64 h60
  text "TOP" at 12562.46,1838.64 h60
  text "X" at 12946.46,1838.64 h60
  text "BOTTOM" at 13073.46,1838.64 h60
  text "SILKSCREEN COLOR:" at 11487.68,1671.64 h60
  text "X" at 12435.42,1671.64 h60
  text "WHITE" at 12562.46,1671.64 h60
  text "OTHER" at 13073.46,1671.64 h60
  text "SOLDER RESIST COLOR:" at 11487.68,1501.64 h60
  text "X" at 12055.42,1342.44 h60
  text "GREEN" at 12182.46,1342.44 h60
  text "BLUE" at 12773.46,1342.44 h60
  text "OTHER" at 13311.46,1342.44 h60
  text "IMMERSION GOLD (ENIG)" at 12393.46,1153.92 h60
  text "SURFACE FINISH:" at 11332.46,1149.64 h60
  text "IMM. TIN/SILVER OR EQUIV" at 11662,992.64 h60
  text "OTHER" at 13093.46,992.64 h60
  text "X" at 11500,990 h60
  text "ARRAY/PANEL:" at 11332.46,813.64 h60
  text "X" at 12200,810 h60
  text "CUT AND TRIM PER MECH LAYER 1" at 12393.46,809.35 h60
  text "N.C. ROUTE" at 12393.46,657.64 h60
  text "V. SCORE" at 13259.46,657.64 h60
  text "CERTIFICATION:" at 11332.46,520.64 h60
  text "MATERIALS AND WORKMANSHIP FOR ALL PCBS" at 12057.46,520.64 h60
  text "TO MEET OR EXCEED THE REQUIREMENTS OF:" at 12057.46,422.64 h60
  text "X" at 11683.96,286.13 h60
  text "ANSI IPC-A-600F CLASS ->" at 11822.96,286.13 h60
  text "X" at 13462.02,286.13 h60
  text "2" at 13580.96,286.14 h60
  text "1" at 13265.96,284.64 h60
  text "3" at 13934.96,284.64 h60
  text "X" at 11686.02,126.64 h60
  text "UL 94V-0" at 11822.96,126.64 h60
  text "X" at 12498.02,126.64 h60
  text "RoHS" at 12634.96,126.64 h60
  text "OTHER" at 13279.36,126.64 h60
  text "PER ORDER" at 13676.42,126.64 h60
  text "ADDITIONAL REQUIREMENTS:" at 11332.46,-14.36 h60
  text "MICROSECTION:" at 11407.23,-129.36 h60
  text "YES" at 12312.96,-129.36 h60
  text "REQUIRED" at 13174.46,-285.51 h60
  text "BARE BOARD ELEC. TEST:" at 11407.23,-288.36 h60
  text "NONE" at 12712.96,-288.36 h60
  text "PER ORDER" at 13766.46,-288.36 h60
  text "X" at 12590,-290 h60
  text "MANUFACTURER'S ID/LOGO:" at 11407.23,-445.36 h60
  text "RAIL" at 12872.96,-449.65 h60
  text "METAL" at 13364.77,-449.65 h60
  text "X" at 13740,-450 h60
  text "SILK" at 13876.46,-449.65 h60
  text ".Layer_Name" at 577,-2258.49 h60
M11 Gerber Information:
  lines w10: -292,-2330.17 6308,-2330.17 ; -292,-2126.83 6310,-2126.83 ; -292,-1923.5 -292,-2533.5 3713,-2533.5 6310,-2533.5 6310,-1923.5 -291.5,-1923.5 -291.5,-2533.5 1284,-2533.5 ; 2173,-2533.5 2173,-1923.5 ; 3440,-2126.83 3440,-1923.5 ; 4280,-2126.83 4280,-1923.5 ; 4902,-2540 4902,-2337.17
  text "ALL ARTWORK VIEWED FROM TOP SIDE" at -228.5,-2055.67 h60
  text "BOARD #:" at 2248,-2055.67 h60
  text ".PRJ_Number" at 2793.5,-2055.67 h60
  text "REV:" at 3638,-2055.67 h60
  text ".PCB_Rev" at 3929.5,-2055.67 h60
  text "SVN REV:" at 4476,-2055.67 h60
  text ".VersionControl_RevNumber" at 4982,-2055.67 h60
  text "LAYER NAME =" at -228.5,-2258.49 h60
  text "PLOT NAME =" at -228.5,-2464.34 h60
  text ".plot_File_Name" at 577,-2464.34 h60
  text "GENERATED    :" at 2250,-2464.34 h60
  text ".Print_Date" at 3119.5,-2464.34 h60
  text ".Print_Time" at 3848.5,-2464.34 h60
  text "TEXAS INSTRUMENTS" at 5113,-2464.34 h60
M12 Stackup:
  lines w9: 6790,5162 10860,5162 ; 6790,5326.8 10860,5326.8 ; 6730,4123 ccw(c6783,4123) 6783,4070 10867,4070 ccw(c10867,4123) 10920,4123 10920,5467 ccw(c10867,5467) 10867,5520 6783,5520 ccw(c6783,5467) 6730,5467 6730,4123
  text "Layer Stack Up Detail for: PMP9334 RevB.PcbDoc" at 6790,5368.7 h74
  text "Layer" at 6790,5265.3 h38
  text "Gerber" at 8217.38,5265.3 h38
  text "Copper" at 9132.85,5265.3 h38
  text "Dielectric" at 10110.37,5265.3 h38
  text "Name" at 6790,5189.3 h38
  text "Document" at 8217.38,5189.3 h38
  text "Thickness" at 9132.85,5189.3 h38
  text "Material" at 10110.37,5189.3 h38
  text "Top Solder Mask" at 6790,5081.98 h53
  text "(.GTS)" at 8217.38,5081.98 h53
  text "Solder Resist" at 10110.37,5081.98 h53
  text "Top Layer" at 6790,4930.94 h53
  text "(.GTL)" at 8217.38,4930.94 h53
  text "1.4mil" at 9132.85,4930.94 h53
  text "FR-4" at 10110.37,4855.42 h53
  text "MidLayer1" at 6790,4779.9 h53
  text "(.G1)" at 8217.38,4779.9 h53
  text "0.7mil" at 9132.85,4779.9 h53
  text "FR-4" at 10110.37,4704.38 h53
  text "GND" at 6790,4628.85 h53
  text "(.G2)" at 8217.38,4628.85 h53
  text "0.7mil" at 9132.85,4628.85 h53
  text "FR-4" at 10110.37,4553.33 h53
  text "Bottom Layer" at 6790,4477.81 h53
  text "(.GBL)" at 8217.38,4477.81 h53
  text "1.4mil" at 9132.85,4477.81 h53
  text "Bottom Solder Mask" at 6790,4326.77 h53
  text "(.GBS)" at 8217.38,4326.77 h53
  text "Solder Resist" at 10110.37,4326.77 h53
  text ".Layer_Name" at 577,-2258.49 h60
M13 Component Bodies Top:
  text ".Layer_Name" at 577,-2258.49 h60
M14 Component Bodies Bottom:
  text ".Layer_Name" at 577,-2258.49 h60
M15 Courtyards Top:
  text ".Layer_Name" at 577,-2258.49 h60
M16 Courtyards Bottom:
  text ".Layer_Name" at 577,-2258.49 h60
Drill Drawing:
  text ".legend" at 5122.5,-674.5 h60
  text "Drill Table" at 5147.5,-859.5 h60
  text ".Layer_Name" at 577,-2258.49 h60

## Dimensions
1,25 to 4000,0 on M2 Board Dimensions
